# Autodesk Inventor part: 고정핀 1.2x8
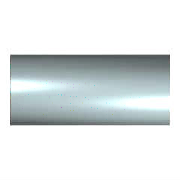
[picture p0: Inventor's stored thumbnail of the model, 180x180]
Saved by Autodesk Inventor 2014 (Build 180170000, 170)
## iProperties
IsCustomPart: 1
Created: 2012-02
Part Number: 고정핀 1.2x8
Material: 강철, 연강
Description: 평행 핀
Document SubType Name: Modeling
Standard: KS B 1320
Designer: P15F
Standards Organization: KS
Language: ko-KR
Size Designation: C 1.2 x  8
Categories: <MemberInstance><Categories><Category DisplayName="조임쇠" InternalName="e4da775c-781d-43d5-af7c-5136215cf5a6" Mnemonic="FSTN"><Category DisplayName="핀" InternalNa
Density: 1 g/cm^3
Appearance: 노란색
Author: P15F
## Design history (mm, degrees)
sketch "스케치1"
  geometry: C1 r 0.6 at (0, 0); 1 further point
  constraints: 1 centre point, 1 coincident
  dimensions: "d1" = 1.2 diameter of C1 (= NND)
extrude "본체" new body sketch "스케치1" distance "d2" = 8 (= NLG); taper "d3" = 0 deg
node "작업 평면1"
body "Solid1"
other parameters: "NND" = 1.2 [user parameter; used in 1 equation term], "NLG" = 8 [user parameter; used in 1 equation term], "d8" = 0, "d9" = 0, "d10" = 0
